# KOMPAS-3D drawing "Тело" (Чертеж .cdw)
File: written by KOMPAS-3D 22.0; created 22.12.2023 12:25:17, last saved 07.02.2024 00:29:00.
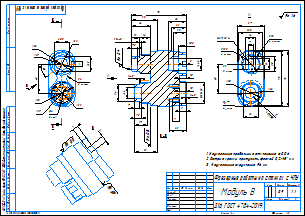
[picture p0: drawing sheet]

Sheet 1: A3, landscape

Document properties: Автор: Админ; Масса: 0.901045

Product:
- Body: Тело 1
    Масса: 0.932078
- Part/product: Тело
    Масса: 0.901045
    Форматы листов документа: A3

Title block, sheet 1: Наименование: Модуль В; designation: Фрезерные работы на станках с ЧПУ; Материал: Д16 ГОСТ 4784-2019; Масса: 0,9; Количество листов документа: 1; Форматы листов документа: A3; stored path: D:\ГЛАВНЮК\ГЭ Москвы\Регион 2023-24\КД 2024 РЧ\Юниоры\КЗ\Бин.cdw

Views: Вид 1, Спереди, Разрез А-А, Вид по стрелке 3, Вид по стрелке 4, Разрез В-В, Вид по стрелке А, Вид по стрелке Б
Referenced files in D:\ГЛАВНЮК\ГЭ Москвы\Регион 2023-24\КД 2024 РЧ\Юниоры\КЗ\: проба юниоры.m3d
Referenced files in C:\Users\User\YandexDisk\МК\КД 2024 РЧ\Основная\КЗ\Вариант №2\Пакет для региона №2\: Модуль А.m3d
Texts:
  1. Неуказанные предельные отклонения ± 0,06
  2. Острые кромки притупить фаской 0,2x45° мм
  3.  Неуказанные скругления R6 мм.
  Ra 0,8
  Ra 0,4
  Ra 0.6
  Ra 1.6
Dimensions and other numbers on the sheet: 35; 32; 27; 20,5; 40; 6; 2 места; 7; 19; 6 отв.; 33; 21,5; 75; 26; 11; 7,5; 31; 17; 9,5; 24; 16; 1; 21; 18; 10,5; 5; 9; 30; 23; 25; 16,5; 14; 1,5; 10; 37; 78; 15; 4 места; 32,5; 20; 13,5; 36; 3; 8 мест; 6 мест; 8; 1:1; 0,9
